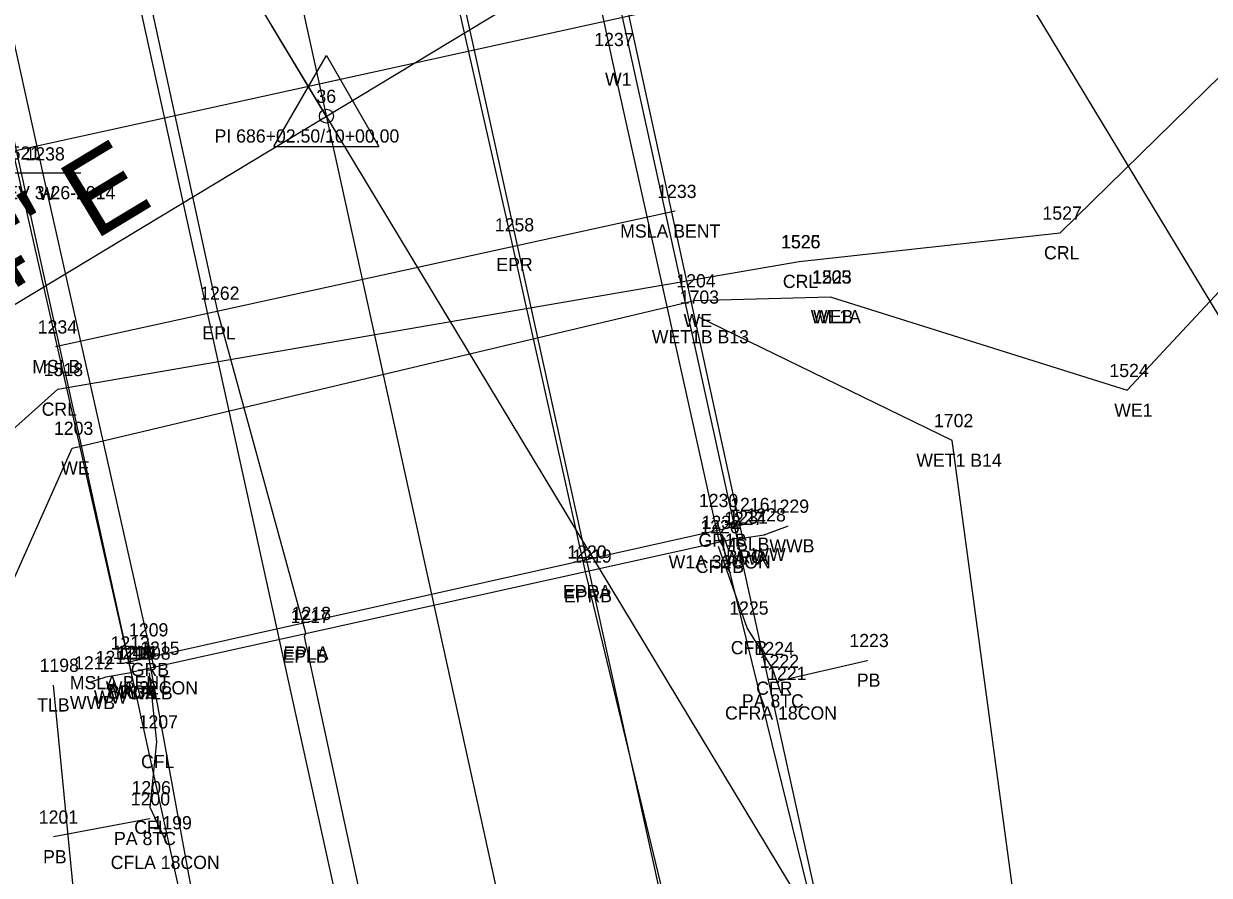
# Model space of a CAD drawing. Extents: x 2522090 to 2524658, y 882711 to 887512.
# Drawn here: x 2523766.8 to 2523856.5, y 885062.2 to 885126.7 of the extents above; entities that cross this region are included whole.
import ezdxf

# ---------------------------------------------------------------- set-up
doc = ezdxf.new("R2010")
doc.units = 0
for name, color, linetype in [('RD_EV_JurisArea', 7, 'Continuous'), ('RD_EX_BldgApp', 7, 'Continuous'), ('RD_EX_BldgApp_txCode', 7, 'Continuous'), ('RD_EX_Bridge', 7, 'Continuous'), ('RD_EX_Bridge_txCode', 7, 'Continuous'), ('RD_EX_Conc', 7, 'Continuous'), ('RD_EX_Conc_txCode', 7, 'Continuous'), ('RD_EX_DR_Pipe', 7, 'Continuous'), ('RD_EX_DR_Pipe_txCode', 7, 'Continuous'), ('RD_EX_GuardRail', 7, 'Continuous'), ('RD_EX_GuardRail_txCode', 7, 'Continuous'), ('RD_EX_H2O', 7, 'Continuous'), ('RD_EX_H2O_txCode', 7, 'Continuous'), ('RD_EX_H2O_WetLd_txCode', 7, 'Continuous'), ('RD_EX_Misc', 7, 'Continuous'), ('RD_EX_Misc_txCode', 7, 'Continuous'), ('RD_EX_Road', 7, 'Continuous'), ('RD_EX_Road_txCode', 7, 'Continuous'), ('RD_EX_VEG', 7, 'Continuous'), ('RD_EX_VEG_txCode', 7, 'Continuous'), ('RD_HC_Cl', 7, 'Continuous'), ('RD_HC_Data', 7, 'Continuous'), ('RD_HC_Data_Tic', 7, 'Continuous'), ('RD_HC_txCode', 7, 'Continuous'), ('RD_PD_Bridge', 7, 'Continuous'), ('RD_PD_Final_TrvlWay', 7, 'Continuous'), ('RD_PD_PatLn5', 7, 'Continuous'), ('RD_PD_PatLn6', 7, 'Continuous'), ('RD_SMD_Locator', 7, 'Continuous')]:
    doc.layers.add(name, color=color, linetype=linetype)

msp = doc.modelspace()

# ---------------------------------------------------------------- linework, layer by layer
at = {"layer": 'RD_EV_JurisArea'}
msp.add_lwpolyline([(2523944.864, 884550.08), (2523910.413, 884709.577), (2523888.007, 884815.03), (2523863.93, 884918.366), (2523848.427, 885010.841), (2523837.066, 885095.132), (2523817.825, 885104.474)], dxfattribs=at)
at = {"layer": 'RD_EX_BldgApp'}
for points in [[(2523819.439, 885087.441), (2523811.319, 885123.961), (2523803.308, 885161.503)], [(2523776.677, 885077.915), (2523768.273, 885115.309), (2523760.204, 885151.895)]]:
    msp.add_lwpolyline(points, dxfattribs=at)
at = {"layer": 'RD_EX_Bridge'}
for points in [[(2523774.906, 885077.596), (2523821.197, 885087.829), (2523805.064, 885161.895), (2523758.145, 885151.437), (2523774.906, 885077.596)], [(2523821.146, 885087.728), (2523822.84, 885087.999), (2523824.599, 885088.655)], [(2523774.897, 885077.54), (2523773.018, 885077.212), (2523771.668, 885076.8)]]:
    msp.add_lwpolyline(points, dxfattribs=at)
at = {"layer": 'RD_EX_Conc'}
for points in [[(2523824.118, 885076.01), (2523823.453, 885077.886), (2523821.532, 885080.953), (2523819.362, 885087.102)], [(2523777.605, 885064.707), (2523776.362, 885067.363), (2523776.876, 885072.337), (2523776.323, 885077.543)]]:
    msp.add_lwpolyline(points, dxfattribs=at)
at = {"layer": 'RD_EX_DR_Pipe'}
for p, q in [((2523823.84, 885076.923), (2523830.626, 885078.493)), ((2523776.322, 885066.515), (2523769.037, 885065.137))]:
    msp.add_line(p, q, dxfattribs=at)
at = {"layer": 'RD_EX_GuardRail'}
for points in [[(2523841.112, 885013.814), (2523827.604, 885055.265), (2523819.275, 885089.086)], [(2523787.377, 885001.584), (2523782.908, 885042.685), (2523776.151, 885079.302)]]:
    msp.add_lwpolyline(points, dxfattribs=at)
at = {"layer": 'RD_EX_H2O'}
for points in [[(2523582.816, 884766.342), (2523598.112, 884856.984), (2523627.586, 884901.753), (2523623.762, 884928.278), (2523586.58, 884955.428), (2523600.942, 884974.118), (2523633.055, 884997.681), (2523679.166, 885037.048), (2523744.717, 885076.895), (2523769.376, 885098.995), (2523825.47, 885108.66), (2523825.47, 885108.66), (2523845.237, 885110.828), (2523890.252, 885154.934), (2523858.435, 885178.041), (2523850.814, 885196.928), (2523892.509, 885249.744), (2523936.89, 885290.086), (2523980.857, 885285.467), (2524009.058, 885269.77), (2524037.386, 885280.087)], [(2523827.825, 885105.996), (2523850.303, 885098.921), (2523867.326, 885117.194), (2523890.438, 885097.244), (2523927.793, 885098.781), (2523966.352, 885109.501), (2523978.174, 885083.367)], [(2523792.732, 884941.121), (2523763.674, 885051.555), (2523756.264, 885062.719), (2523770.471, 885094.548), (2523817.567, 885105.706), (2523827.825, 885105.996)]]:
    msp.add_lwpolyline(points, dxfattribs=at)
at = {"layer": 'RD_EX_Misc'}
for p, q in [((2523761.128, 885115.375), (2523771.128, 885115.375)), ((2523816.084, 885112.468), (2523769.205, 885102.217)), ((2523774.429, 885078.307), (2523821.346, 885088.784))]:
    msp.add_line(p, q, dxfattribs=at)
at = {"layer": 'RD_EX_Road'}
for p, q in [((2523803.791, 885109.941), (2523798.302, 885134.145)), ((2523781.516, 885104.768), (2523776.178, 885129.21)), ((2523809.315, 885085.19), (2523803.791, 885109.941)), ((2523788.138, 885080.544), (2523781.516, 885104.768)), ((2523809.375, 885084.881), (2523809.315, 885085.19)), ((2523817.578, 885050.917), (2523809.375, 885084.881)), ((2523788.047, 885080.306), (2523788.138, 885080.544)), ((2523795.465, 885045.906), (2523788.047, 885080.306))]:
    msp.add_line(p, q, dxfattribs=at)
at = {"layer": 'RD_EX_VEG'}
msp.add_lwpolyline([(2523800.231, 884418.22), (2523892.245, 884498.974), (2523844.575, 884752.813), (2523771.945, 885046.883), (2523769.056, 885076.621)], dxfattribs=at)
at = {"layer": 'RD_HC_Cl'}
for p, q in [((2523641.165, 885794.201), (2524197.759, 883266.557)), ((2523672.044, 885048.634), (2523837.18, 885148.323))]:
    msp.add_line(p, q, dxfattribs=at)
at = {"layer": 'RD_HC_Data'}
for p, q in [((2523785.73, 885117.368), (2523789.702, 885124.248)), ((2523789.702, 885124.248), (2523793.671, 885117.368)), ((2523785.73, 885117.368), (2523793.671, 885117.368))]:
    msp.add_line(p, q, dxfattribs=at)
msp.add_circle((2523789.701, 885119.661), 0.529, dxfattribs=at)
at = {"layer": 'RD_HC_Data_Tic'}
for p, q in [((2523789.692, 885119.656), (2523785.558, 885126.504)), ((2523789.164, 885122.1), (2523793.07, 885122.96)), ((2523789.692, 885119.656), (2523793.827, 885112.807))]:
    msp.add_line(p, q, dxfattribs=at)
at = {"layer": 'RD_PD_Bridge'}
for points in [[(2523830.93, 885041.703), (2523794.372, 885207.726)], [(2523748.471, 885197.618), (2523785.03, 885031.596)]]:
    msp.add_lwpolyline(points, dxfattribs=at)
at = {"layer": 'RD_PD_Final_TrvlWay'}
for p, q in [((2523722.39, 885481.141), (2524037.438, 884050.417)), ((2523698.951, 885475.979), (2524014, 884045.256))]:
    msp.add_line(p, q, dxfattribs=at)
at = {"layer": 'RD_PD_PatLn5'}
msp.add_line((2523877.058, 885141.454), (2523711.036, 885104.896), dxfattribs=at)
at = {"layer": 'RD_PD_PatLn6'}
for p, q in [((2523791.153, 885213.984), (2523873.842, 885077.008)), ((2523748.348, 885188.144), (2523831.037, 885051.167))]:
    msp.add_line(p, q, dxfattribs=at)
at = {"layer": 'RD_SMD_Locator'}
for centre in [(2523811.319, 885123.961), (2523789.701, 885119.661), (2523768.273, 885115.309), (2523816.084, 885112.468), (2523845.237, 885110.828), (2523803.791, 885109.941), (2523825.47, 885108.66), (2523825.47, 885108.66), (2523817.567, 885105.706), (2523827.825, 885105.996), (2523827.825, 885105.996), (2523781.516, 885104.768), (2523817.825, 885104.474), (2523769.205, 885102.217), (2523769.376, 885098.995), (2523850.303, 885098.921), (2523770.471, 885094.548), (2523837.066, 885095.132), (2523819.275, 885089.086), (2523821.346, 885088.784), (2523824.599, 885088.655), (2523819.439, 885087.441), (2523821.146, 885087.728), (2523821.197, 885087.829), (2523822.84, 885087.999), (2523819.362, 885087.102), (2523809.315, 885085.19), (2523809.375, 885084.881), (2523821.532, 885080.953), (2523788.047, 885080.306), (2523788.138, 885080.544), (2523776.151, 885079.302), (2523774.429, 885078.307), (2523830.626, 885078.493), (2523774.897, 885077.54), (2523774.906, 885077.596), (2523774.906, 885077.596), (2523776.323, 885077.543), (2523776.677, 885077.915), (2523823.453, 885077.886), (2523769.056, 885076.621), (2523771.668, 885076.8), (2523773.018, 885077.212), (2523823.84, 885076.923), (2523824.118, 885076.01), (2523776.876, 885072.337), (2523776.362, 885067.363), (2523776.322, 885066.515), (2523769.037, 885065.137), (2523777.605, 885064.707)]:
    msp.add_circle(centre, 0.001, dxfattribs=at)

# ---------------------------------------------------------------- texts
at = {"layer": 'RD_EX_BldgApp_txCode'}
for s, p in [('1237', (2523809.973, 885124.961)), ('W1', (2523810.784, 885121.961)), ('1238', (2523766.926, 885116.309)), ('W', (2523767.903, 885113.309)), ('1232', (2523818.093, 885088.441)), ('W1A 32CON', (2523815.597, 885085.441)), ('1215', (2523775.614, 885078.915)), ('WA 32CON', (2523773, 885075.915))]:
    msp.add_text(s, height=1, dxfattribs=at).set_placement(p)
at = {"layer": 'RD_EX_Bridge_txCode'}
for s, p in [('1228', (2523821.494, 885088.999)), ('1229', (2523823.253, 885089.655)), ('1227', (2523819.799, 885088.728)), ('1231', (2523820.134, 885088.829)), ('WWB', (2523823.221, 885086.655)), ('WWA', (2523819.752, 885085.728)), ('BRC', (2523819.945, 885085.829)), ('WW', (2523821.934, 885085.999)), ('1211', (2523772.238, 885078.212)), ('1246', (2523773.536, 885078.596)), ('1210', (2523773.795, 885078.54)), ('1214', (2523773.843, 885078.596)), ('1212', (2523770.605, 885077.8)), ('BRCA', (2523773.166, 885075.596)), ('BRCB', (2523773.182, 885075.596)), ('WWA', (2523773.503, 885075.54)), ('WWB', (2523770.29, 885074.8)), ('WW', (2523772.112, 885075.212))]:
    msp.add_text(s, height=1, dxfattribs=at).set_placement(p)
at = {"layer": 'RD_EX_Conc_txCode'}
for s, p in [('1226', (2523817.992, 885088.102)), ('CFRB', (2523817.661, 885085.102)), ('1225', (2523820.185, 885081.953)), ('1208', (2523774.937, 885078.543)), ('CFR', (2523820.303, 885078.953)), ('1224', (2523822.107, 885078.886)), ('1221', (2523823.055, 885077.01)), ('CFLB', (2523774.646, 885075.543)), ('CFR', (2523822.225, 885075.886)), ('CFRA 18CON', (2523819.866, 885074.01)), ('1207', (2523775.491, 885073.337)), ('CFL', (2523775.672, 885070.337)), ('1206', (2523774.952, 885068.363)), ('1199', (2523776.542, 885065.707)), ('CFL', (2523775.157, 885065.363)), ('CFLA 18CON', (2523773.377, 885062.707))]:
    msp.add_text(s, height=1, dxfattribs=at).set_placement(p)
at = {"layer": 'RD_EX_DR_Pipe_txCode'}
for s, p in [('1223', (2523829.28, 885079.493)), ('1222', (2523822.493, 885077.923)), ('PB', (2523829.846, 885076.493)), ('PA 8TC', (2523821.147, 885074.923)), ('1200', (2523774.897, 885067.515)), ('1201', (2523767.935, 885066.137)), ('PA 8TC', (2523773.629, 885064.515)), ('PB', (2523768.257, 885063.137))]:
    msp.add_text(s, height=1, dxfattribs=at).set_placement(p)
at = {"layer": 'RD_EX_GuardRail_txCode'}
for s, p in [('1230', (2523817.89, 885090.086)), ('GR1B', (2523817.858, 885087.086)), ('1209', (2523774.765, 885080.302)), ('GRB', (2523774.899, 885077.302))]:
    msp.add_text(s, height=1, dxfattribs=at).set_placement(p)
at = {"layer": 'RD_EX_H2O_txCode'}
for s, p in [('1527', (2523843.89, 885111.828)), ('1526', (2523824.1, 885109.66)), ('1525', (2523824.124, 885109.66)), ('CRL', (2523844.008, 885108.828)), ('1205', (2523826.44, 885106.996)), ('1523', (2523826.479, 885106.996)), ('1204', (2523816.181, 885106.706)), ('CRL', (2523824.242, 885106.66)), ('CRL', (2523824.242, 885106.66)), ('WE', (2523816.729, 885103.706)), ('WE1A', (2523826.353, 885103.996)), ('WEB', (2523826.534, 885103.996)), ('1518', (2523768.313, 885099.995)), ('1524', (2523848.957, 885099.921)), ('CRL', (2523768.148, 885096.995)), ('WE1', (2523849.319, 885096.921)), ('1203', (2523769.085, 885095.548)), ('WE', (2523769.632, 885092.548))]:
    msp.add_text(s, height=1, dxfattribs=at).set_placement(p)
at = {"layer": 'RD_EX_H2O_WetLd_txCode'}
for s, p in [('1703', (2523816.439, 885105.474)), ('WET1B B13', (2523814.321, 885102.474)), ('1702', (2523835.68, 885096.132)), ('WET1 B14', (2523834.341, 885093.132))]:
    msp.add_text(s, height=1, dxfattribs=at).set_placement(p)
at = {"layer": 'RD_EX_Misc_txCode'}
for s, p in [('1521', (2523765.065, 885116.375)), ('MSP WATER ELEV 3-26-2014', (2523755.372, 885113.375)), ('1233', (2523814.737, 885113.468)), ('MSLA BENT', (2523811.934, 885110.468)), ('1234', (2523767.858, 885103.217)), ('MSLB', (2523767.441, 885100.217)), ('1216', (2523820.259, 885089.784)), ('MSLB', (2523819.582, 885086.784)), ('1213', (2523773.366, 885079.307)), ('MSLA BENT', (2523770.279, 885076.307))]:
    msp.add_text(s, height=1, dxfattribs=at).set_placement(p)
at = {"layer": 'RD_EX_Road_txCode'}
for s, p in [('1258', (2523802.445, 885110.941)), ('EPR', (2523802.563, 885107.941)), ('1262', (2523780.146, 885105.768)), ('EPL', (2523780.311, 885102.768)), ('1220', (2523807.93, 885086.19)), ('1219', (2523808.312, 885085.881)), ('EPRA', (2523807.599, 885083.19)), ('EPRB', (2523807.675, 885082.881)), ('1217', (2523786.984, 885081.306)), ('1218', (2523787.075, 885081.544)), ('EPLB', (2523786.37, 885078.306)), ('EPLA', (2523786.445, 885078.544))]:
    msp.add_text(s, height=1, dxfattribs=at).set_placement(p)
at = {"layer": 'RD_EX_VEG_txCode'}
for s, p in [('1198', (2523767.993, 885077.621)), ('TLB', (2523767.812, 885074.621))]:
    msp.add_text(s, height=1, dxfattribs=at).set_placement(p)
at = {"layer": 'RD_HC_Data'}
msp.add_text('N 58%%d 52\' 54" E', height=6, rotation=31.1184, dxfattribs=at).set_placement((2523730.142, 885084.875))
at = {"layer": 'RD_HC_txCode'}
for s, p in [('36', (2523788.945, 885120.661)), ('PI 686+02.50/10+00.00', (2523781.236, 885117.661))]:
    msp.add_text(s, height=1, dxfattribs=at).set_placement(p)

doc.saveas('drawing.dxf')
